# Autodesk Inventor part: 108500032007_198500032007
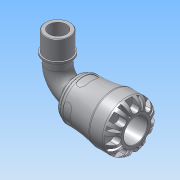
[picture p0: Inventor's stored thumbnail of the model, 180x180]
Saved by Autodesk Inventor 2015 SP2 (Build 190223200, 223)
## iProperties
Created: 2016-12
Part Number: 108500032007_198500032007
Material: PVC-Piping
Description: PLASSON 90° ELBOW WITH THREADED MALE OFFTAKE 32X3/4" SERIES 1
Document SubType Name: Modeling
Designer: KIM
Mass: 664.223 g
Surface Area: 733.008 cm^2
Volume: 474.445 cm^3
Density: 1.4 g/cm^3
Appearance: Smooth - White
Author: KIM
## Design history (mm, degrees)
derived "1085.ipt"
feature "Solid1::1085.ipt"
tag "TaggingFeature1"
body "Solid1"
other parameters: "d1" = 22.26, "d2" = 32, "d4" = 58, "d8" = 49.3, "d13" = 7.2, "d14" = 7.2, "d15" = 0, "d17" = 360 deg, "d19" = 8 deg, "d20" = 0.64, "d21" = 0.64, "d22" = 8 deg, "d24" = 0, "d26" = 360 deg, "d33" = 5.8, "d43" = 45.24, "d51" = 0.58, "d54" = 11.2, "d55" = 7.04, "d57" = 14.112, "d58" = 0, "d74" = 0, "d78" = 53, "d82" = 0.64, "d115" = 360 deg, "d207" = 90 deg, "d228" = 9.52, "d247" = 1.16, "d248" = 3.18, "d268" = 27.115, "d269" = 3.18, "d270" = 81, "d276" = 26.441, "d277" = 17, "d278" = 29.0851, "d279" = 51, "d280" = 18.7, "d281" = 3.96615, "d283" = 23.7969, "d286" = 0, "d287" = 0, "d288" = 18.5087, "d290" = 10.72155, "d292" = 30 deg, "d_" = 32, "E_" = 58, "l_" = 53, "A_" = 81, "A_1" = 51, "l_2" = 17, "R_" = 26.441, "d9" = 9, "d11" = 58, "d289" = 18.5087
